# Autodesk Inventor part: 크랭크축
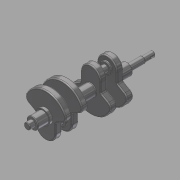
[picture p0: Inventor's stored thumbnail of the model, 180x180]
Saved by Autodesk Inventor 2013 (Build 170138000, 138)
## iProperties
Created: 2017-03
Part Number: 크랭크축
Material: 강철, 탄소
Document SubType Name: Modeling
Designer: mduedu
Density: 7.87 g/cm^3
Mass: 1840.77 g
Surface Area: 500.249 cm^2
Volume: 233.897 cm^3
Author: mduedu
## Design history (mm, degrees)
sketch "스케치1" dims "d5" = 57
  geometry: L1 (-19, 21.243)-(-19, 3.243); L2 (-19, 3.243)-(-40.023, -8.895); L3 (19, 21.243)-(19, 3.243); L4 (0, 21.243)-(0, -41); L5 (19, 3.243)-(40.023, -8.895); C1 r 6 at (0, 0); C2 r 13.5 at (0, 0); A1 r 41 centre (0, 0) between (-40.023, -8.895) and (0, -41); A2 r 41 centre (0, 0) between (0, -41) and (40.023, -8.895); A3 r 19 centre (0, 21.243) between (19, 21.243) and (0, 40.243); A4 r 19 centre (0, 21.243) between (0, 40.243) and (-19, 21.243); 3 further points
  constraints: 10 end point, 8 point on circle, 6 centre point, 5 coincident, 3 symmetric about line, 2 point on line, 1 parallel, 1 tangent, 1 vertical, 1 vertical alignment, 5 other
  dimensions: "d0" = 12 diameter of C1; "d1" = 27 diameter of C2; "d2" = 18 distance of L1.start L1.end; "d3" = 120 deg angle of L2 L1; "d4" = 41 radius of A1; "d6" = 19 radius of A4
extrude "돌출1" new body sketch "스케치1" distance "d7" = 12; taper "d8" = 0 deg
extrude "돌출2" join sketch "스케치1" distance "d9" = 5; taper "d10" = 0 deg
extrude "돌출3" join sketch "스케치1" distance "d11" = 75; taper "d12" = 0 deg
sketch "스케치2"
  geometry: C1 r 11 at (0, 21.243); C2 r 6 at (0, 21.243); A1 r 19 centre (0, 21.243) between (19, 21.243) and (-19, 21.243) reference; 1 further point
  constraints: 2 centre point, 2 coincident
  dimensions: "d13" = 22 diameter of C1; "d14" = 12 diameter of C2
extrude "돌출4" join sketch "스케치2" distance "d15" = 3; taper "d16" = 0 deg
extrude "돌출5" join sketch "스케치2" distance "d17" = 16; taper "d18" = 0 deg
fillet "모깎기1" dims "d19" = 3, "d20" = 10
fillet "모깎기2" dims "d21" = 2
sketch "스케치3"
  geometry: C1 r 11 at (0, 0); 1 further point
  constraints: 1 centre point, 1 coincident
  dimensions: "d22" = 22 diameter of C1
extrude "돌출6" join sketch "스케치3" distance "d23" = 21; taper "d24" = 0 deg
sketch "스케치4"
  geometry: C1 r 6 at (0, 0) reference; C2 r 5 at (0, 0); 1 further point
  constraints: 1 centre point
  dimensions: "d25" = 1 radial gap between concentric circles of C1 C2
extrude "돌출7" cut sketch "스케치4" distance "d26" = 20; taper "d27" = 0 deg
node "작업 평면1"
sketch "스케치5"
  geometry: L1 (-5, 0)-(5, 0) reference; L2 (-1.5, 0)-(1.5, 0); L3 (1.5, 0)-(1.5, 8.5); L4 (-1.5, 8.5)-(-1.5, 0); A1 r 1.5 centre (0, 8.5) between (1.5, 8.5) and (-1.5, 8.5); 1 further point
  constraints: 6 end point, 2 point on circle, 2 tangent, 1 centre point, 1 horizontal, 1 parallel, 1 perpendicular, 1 point on line, 1 vertical alignment
  dimensions: "d28" = 3 distance between parallel lines of L3 L4; "d30" = 10 dimension on A1 L1
extrude "돌출8" cut sketch "스케치5" distance "d31" = 1.8; taper "d32" = 0 deg
chamfer "모따기1" distance "d33" = 1; stored, may be unused: second distance "d34" = 2, angle "d35" = 45 deg
chamfer "모따기2" distance "d36" = 1; stored, may be unused: second distance "d37" = 2, angle "d38" = 45 deg
node "작업 평면2"
sketch "스케치6"
  geometry: C1 r 11 at (0, 0) reference; C2 r 11 at (0, 0) reference; 1 further point
extrude "돌출9" join sketch "스케치6" distance "d39" = 42; taper "d40" = 0 deg
sketch "스케치7" dims "d46" = 57
  geometry: L1 (-19, -21.243)-(-19, -3.243); L2 (19, -21.243)-(19, -3.243); L3 (-19, -3.243)-(-40.023, 8.895); L4 (19, -3.243)-(40.023, 8.895); L5 (0, -21.243)-(0, 41); C1 r 13.5 at (0, 0); C2 r 6 at (0, 0); A1 r 19 centre (0, -21.243) between (0, -40.243) and (19, -21.243); A2 r 19 centre (0, -21.243) between (-19, -21.243) and (0, -40.243); A3 r 41 centre (0, 0) between (0, 41) and (-40.023, 8.895); A4 r 41 centre (0, 0) between (40.023, 8.895) and (0, 41); 3 further points
  constraints: 10 end point, 8 point on circle, 6 centre point, 5 coincident, 3 symmetric about line, 2 point on line, 1 parallel, 1 tangent, 1 vertical, 5 other
  dimensions: "d41" = 12 diameter of C2; "d42" = 27 diameter of C1; "d43" = 18 distance of L2.start L2.end; "d44" = 120 deg angle of L4 L2; "d45" = 41 radius of A4; "d47" = 19 radius of A1
extrude "돌출10" join sketch "스케치7" distance "d48" = 12; taper "d49" = 0 deg
sketch "스케치8"
  geometry: C1 r 11 at (0, -21.243); C2 r 6 at (0, -21.243); A1 r 19 centre (0, -21.243) between (-19, -21.243) and (19, -21.243) reference; 1 further point
  constraints: 2 centre point, 2 coincident
  dimensions: "d50" = 22 diameter of C1; "d51" = 12 diameter of C2
extrude "돌출11" join sketch "스케치8" distance "d52" = 3; taper "d53" = 0 deg
extrude "돌출12" join sketch "스케치8" distance "d54" = 16; taper "d55" = 0 deg
fillet "모깎기3" dims "d56" = 3, "d57" = 10
fillet "모깎기4" dims "d58" = 2
chamfer "모따기3" distance "d59" = 1; stored, may be unused: second distance "d60" = 2, angle "d61" = 45 deg
node "작업 평면3"
fillet "모깎기5" dims "d62" = 1
sketch "스케치9"
  geometry: C1 r 13.5 at (0, 0) reference; 1 further point
extrude "돌출13" join sketch "스케치9" distance "d63" = 5; taper "d64" = 0 deg
sketch "스케치10"
  geometry: C1 r 6 at (0, 0) reference; 1 further point
extrude "돌출14" join sketch "스케치10" distance "d65" = 30; taper "d66" = 0 deg
sketch "스케치11"
  geometry: C1 r 11 at (0, 0); 1 further point
  constraints: 1 centre point, 1 coincident
  dimensions: "d67" = 22 diameter of C1
extrude "돌출15" join sketch "스케치11" distance "d68" = 20; taper "d69" = 0 deg
chamfer "모따기4" distance "d70" = 1; stored, may be unused: second distance "d71" = 2, angle "d72" = 45 deg
chamfer "모따기5" distance "d75" = 0.7; stored, may be unused: second distance "d76" = 2, angle "d77" = 30 deg
fillet "모깎기6" dims "d78" = 0.3
node "솔리드1"
mirror "대칭1"
mirror "대칭2"
node "투영된 루프1"
